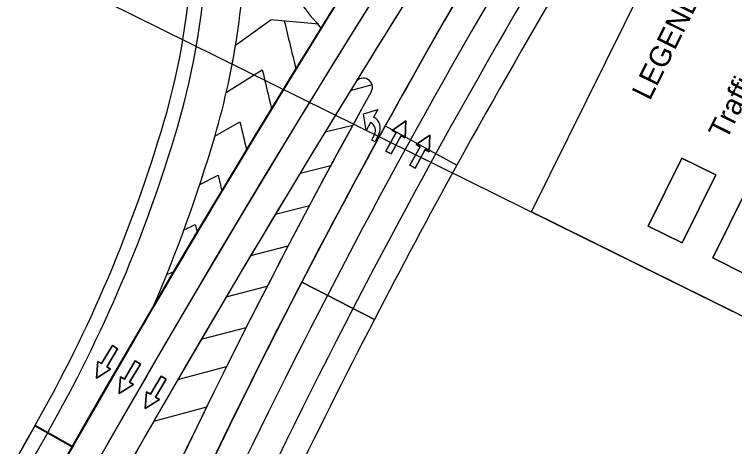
# Model space of a CAD drawing. Extents: x 14090526 to 14125274, y 8637242 to 8677144.
# Drawn here: x 14118917.5 to 14119217.3, y 8668599.6 to 8668779.6 of the extents above; entities that cross this region are included whole.
import ezdxf

# ---------------------------------------------------------------- set-up
doc = ezdxf.new("R2010")
doc.units = 0
for name, color, linetype in [('Cell', 7, 'Continuous'), ('dsn_stg_shd_prev', 7, 'Continuous'), ('dsnNonPlotable', 7, 'Continuous'), ('dsnPaintExistingBrokenLaneLineWhite', 7, 'Continuous'), ('dsnPaintExistingChannelizingLaneWhite', 7, 'Continuous'), ('dsnPaintExistingChannelizingLaneYellow', 7, 'Continuous'), ('dsnPaintExistingEdgeLineRightWhite', 7, 'Continuous'), ('dsnPaintExistingSolidLaneLaneWhite', 7, 'Continuous'), ('dsnShadingPaved', 7, 'Continuous'), ('dsnStgShadingPropPav', 7, 'Continuous'), ('dsnTextOverlapOdd', 7, 'Continuous'), ('Level 2', 7, 'Continuous'), ('Level 5', 7, 'Continuous')]:
    doc.layers.add(name, color=color, linetype=linetype)

msp = doc.modelspace()

# ---------------------------------------------------------------- linework, layer by layer
at = {"layer": 'Cell'}
for p, q in [((14119066.94, 8668736.82), (14119067.1, 8668736.74)), ((14119065.94, 8668734.39), (14119065.66, 8668734.53))]:
    msp.add_line(p, q, dxfattribs=at)
for points in [[(14119062.85, 8668738.26), (14119068.73, 8668740.04), (14119066.94, 8668736.82)], [(14119062.85, 8668738.26), (14119068.73, 8668740.04), (14119066.94, 8668736.82)], [(14119065.66, 8668734.53), (14119063.86, 8668731.31), (14119062.85, 8668738.26)], [(14119065.66, 8668734.53), (14119063.86, 8668731.31), (14119062.85, 8668738.26)], [(14119066.94, 8668736.82), (14119067.1, 8668736.74)], [(14119065.94, 8668734.39), (14119065.66, 8668734.53)], [(14119069.24, 8668729.82), (14119067.61, 8668726.52), (14119066.27, 8668727.19), (14119067.43, 8668729.54)], [(14119069.24, 8668729.82), (14119067.61, 8668726.52), (14119066.27, 8668727.19), (14119067.43, 8668729.54)]]:
    msp.add_lwpolyline(points, dxfattribs=at)
for centre, major_axis in [((14119064.77, 8668732.03), (-2.33, -4.71)), ((14119064.77, 8668732.03), (-2.33, -4.71)), ((14119064.31, 8668731.09), (-1.63, -3.3)), ((14119064.31, 8668731.09), (-1.63, -3.3))]:
    msp.add_ellipse(centre, major_axis=major_axis, ratio=0.9474, start_param=1.570796, end_param=3.141593, dxfattribs=at)
at = {"layer": 'dsn_stg_shd_prev'}
for p, q in [((14119071.87, 8668733.2), (14119101.66, 8668716.8)), ((14118926.04, 8668608.26), (14118941.65, 8668599.39)), ((14118926.13, 8668608.49), (14118941.74, 8668599.61)), ((14118926.13, 8668608.49), (14118941.74, 8668599.61))]:
    msp.add_line(p, q, dxfattribs=at)
for centre, radius, start, end in [((14123732.59, 8665873.82), 5512, 146.41866, 157.1633), ((14123732.59, 8665873.82), 5512, 146.50213, 150.36196), ((14121591.75, 8667345.11), 2876.96, 147.23629, 155.33788), ((14121592.11, 8667345.68), 2876.95, 147.23628, 151.16499), ((14121592.11, 8667345.68), 2842.95, 147.24613, 151.16499), ((14118697.65, 8668817.62), 294, 343.6304, 12.5104), ((14118409.81, 8668902.17), 594, 330.3689, 343.63038), ((14123732.86, 8665874.15), 5530, 150.3689, 156.09911), ((14123732.96, 8665874.38), 5530, 150.3689, 156.09911), ((14123732.59, 8665873.82), 5512, 150.36196, 157.1633)]:
    msp.add_arc(centre, radius, start, end, dxfattribs=at)
at = {"layer": 'dsnNonPlotable'}
msp.add_lwpolyline([(14119315.27, 8668607.09), (14120010, 8670012.23), (14119557.31, 8670236.05), (14118862.58, 8668830.91)], close=True, dxfattribs=at)
at = {"layer": 'dsnPaintExistingBrokenLaneLineWhite'}
for centre, radius, start in [((14121592.11, 8667345.68), 2864.95, 147.15737), ((14123732.96, 8665874.38), 5500, 147.11705)]:
    msp.add_arc(centre, radius, start, 157.1633, dxfattribs=at)
at = {"layer": 'dsnPaintExistingChannelizingLaneWhite'}
for p, q in [((14119009.55, 8668766.85), (14119024.28, 8668777.3)), ((14119044.14, 8668775.58), (14119024.28, 8668777.3)), ((14119005.71, 8668747.22), (14119020.62, 8668756.58)), ((14119000.92, 8668728.83), (14119011.33, 8668734.86)), ((14118994.67, 8668708.79), (14119002.26, 8668712.6)), ((14118988.09, 8668689.91), (14118992.79, 8668692.09)), ((14118980.89, 8668671.25), (14118983.27, 8668672.26))]:
    msp.add_line(p, q, dxfattribs=at)
for centre, radius, start, end in [((14118697.65, 8668817.62), 316, 343.6304, 0.4076), ((14119233.62, 8668936.54), 249, 207.9416, 220.8109), ((14124361.64, 8670051.25), 5482, 193.44292, 193.6584), ((14123732.96, 8665874.38), 5512, 148.26304, 149.67774), ((14124353.66, 8670025.82), 5482, 193.38707, 193.56306), ((14124341.15, 8670017.58), 5482, 193.53196, 193.6584), ((14118409.81, 8668902.17), 616, 336.56541, 343.63038), ((14124330.84, 8670000.44), 5482, 193.58699, 193.6584), ((14124357.11, 8670043.79), 5532, 194.14298, 194.17822), ((14124346.93, 8670026.57), 5532, 194.17092, 194.17822)]:
    msp.add_arc(centre, radius, start, end, dxfattribs=at)
at = {"layer": 'dsnPaintExistingChannelizingLaneYellow'}
for p, q in [((14119066.36, 8668750.3), (14119057.26, 8668747.71)), ((14119046.82, 8668730.65), (14119058.31, 8668733.44)), ((14119036.44, 8668713.55), (14119049.22, 8668716.7)), ((14119026.13, 8668696.42), (14119040.26, 8668699.96)), ((14119015.87, 8668679.24), (14119031.44, 8668683.2)), ((14119005.68, 8668662.04), (14119022.76, 8668666.44)), ((14118995.73, 8668644.44), (14119013.98, 8668649.22)), ((14118985.49, 8668627.51), (14119005.79, 8668632.9)), ((14118975.49, 8668610.19), (14118997.51, 8668616.13))]:
    msp.add_line(p, q, dxfattribs=at)
for centre, radius, start, end in [((14123748.96, 8665864.73), 5506.68, 148.38653, 150.66501), ((14119062.69, 8668749.26), 3.81, 330.9739, 148.3847), ((14121592.11, 8667345.68), 2888.95, 150.97391, 155.3184)]:
    msp.add_arc(centre, radius, start, end, dxfattribs=at)
at = {"layer": 'dsnPaintExistingEdgeLineRightWhite'}
for centre, radius, start, end in [((14121592.11, 8667345.68), 2852.95, 147.15737, 157.1633), ((14118697.65, 8668817.62), 300, 343.6304, 12.5123), ((14118409.81, 8668902.17), 600, 330.3689, 343.63038), ((14123732.96, 8665874.38), 5524, 150.3689, 156.09858)]:
    msp.add_arc(centre, radius, start, end, dxfattribs=at)
at = {"layer": 'dsnPaintExistingSolidLaneLaneWhite'}
msp.add_line((14118975, 8668657.18), (14118941.78, 8668599.59), dxfattribs=at)
msp.add_arc((14121592.11, 8667345.68), 2876.95, 150.94619, 156.23387, dxfattribs=at)
at = {"layer": 'dsnShadingPaved'}
msp.add_line((14118941.78, 8668599.59), (14118931.35, 8668605.52), dxfattribs=at)
for centre, radius, start, end in [((14123732.96, 8665874.38), 5500, 145.2497, 157.1633), ((14123732.96, 8665874.38), 5488, 145.2497, 157.1633), ((14123732.96, 8665874.38), 5500, 146.42378, 157.1633), ((14121592.11, 8667345.68), 2876.95, 147.15737, 157.1633), ((14121592.11, 8667345.68), 2852.95, 147.15737, 157.1633), ((14123655.03, 8665915.77), 5424.12, 146.80648, 157.24675), ((14118697.65, 8668817.62), 300, 343.6304, 12.5123), ((14121592.11, 8667345.68), 2876.95, 149.16283, 157.1633), ((14123732.96, 8665874.38), 5488, 147.75486, 148.38471), ((14123732.96, 8665874.38), 5512, 148.132, 150.3689), ((14119062.69, 8668749.26), 3.81, 330.9739, 148.3847), ((14121592.11, 8667345.68), 2888.95, 150.97391, 156.23389), ((14118409.81, 8668902.17), 600, 330.3689, 343.63038), ((14123732.96, 8665874.38), 5524, 150.3689, 156.09858)]:
    msp.add_arc(centre, radius, start, end, dxfattribs=at)
at = {"layer": 'dsnStgShadingPropPav'}
for p, q in [((14119071.87, 8668733.2), (14119101.66, 8668716.8)), ((14119071.87, 8668733.2), (14119101.66, 8668716.8)), ((14119067.32, 8668652.5), (14119037.13, 8668668.13)), ((14119037.13, 8668668.13), (14119067.32, 8668652.5)), ((14118926.13, 8668608.49), (14118941.74, 8668599.61))]:
    msp.add_line(p, q, dxfattribs=at)
for centre, radius, start, end in [((14123732.59, 8665873.82), 5512, 146.41866, 157.1633), ((14123732.59, 8665873.82), 5512, 146.50213, 150.36196), ((14121591.75, 8667345.11), 2876.96, 147.23629, 155.33788), ((14121592.11, 8667345.68), 2876.95, 147.23628, 151.16499), ((14121592.11, 8667345.68), 2842.95, 147.24613, 151.16499), ((14118697.65, 8668817.62), 294, 343.6304, 12.5104), ((14118409.81, 8668902.17), 594, 330.3689, 343.63038), ((14121592.11, 8667345.68), 2876.95, 151.16499, 152.63404), ((14121592.11, 8667345.68), 2842.95, 151.16499, 152.63404), ((14121592.11, 8667345.68), 2876.95, 152.63404, 155.90343), ((14121592.11, 8667345.68), 2842.95, 152.63404, 155.90343)]:
    msp.add_arc(centre, radius, start, end, dxfattribs=at)
at = {"layer": 'dsnTextOverlapOdd'}
for points in [[(14119132.8, 8668697.31), (14119210.08, 8668853.62), (14119392.55, 8668763.4), (14119315.27, 8668607.09)], [(14119132.8, 8668697.31), (14119210.08, 8668853.62), (14119392.55, 8668763.4), (14119315.27, 8668607.09)], [(14119181.33, 8668691.45), (14119195.33, 8668719.78), (14119209.41, 8668712.82), (14119195.4, 8668684.49)], [(14119209.41, 8668712.82), (14119195.33, 8668719.78), (14119181.33, 8668691.45), (14119195.4, 8668684.49)], [(14119208.22, 8668678.15), (14119222.23, 8668706.49), (14119236.3, 8668699.53), (14119222.29, 8668671.19)], [(14119236.3, 8668699.53), (14119222.23, 8668706.49), (14119208.22, 8668678.15), (14119222.29, 8668671.19)]]:
    msp.add_lwpolyline(points, close=True, dxfattribs=at)
at = {"layer": 'Level 2'}
for points in [[(14119072.11, 8668722.7), (14119074.3, 8668721.49), (14119078.53, 8668729.15), (14119080.17, 8668728.24), (14119080.46, 8668735.22), (14119074.71, 8668731.27), (14119076.35, 8668730.36)], [(14119082.1, 8668716.83), (14119084.28, 8668715.62), (14119088.52, 8668723.28), (14119090.16, 8668722.37), (14119090.45, 8668729.36), (14119084.69, 8668725.4), (14119086.33, 8668724.49)], [(14118960.4, 8668640.37), (14118958.25, 8668641.66), (14118953.77, 8668634.14), (14118952.16, 8668635.1), (14118951.64, 8668628.14), (14118957.52, 8668631.9), (14118955.91, 8668632.86)], [(14118969.91, 8668633.96), (14118967.76, 8668635.25), (14118963.28, 8668627.73), (14118961.67, 8668628.69), (14118961.15, 8668621.72), (14118967.04, 8668625.49), (14118965.43, 8668626.45)], [(14118980.7, 8668627.64), (14118978.55, 8668628.93), (14118974.07, 8668621.41), (14118972.46, 8668622.37), (14118971.94, 8668615.41), (14118977.82, 8668619.17), (14118976.21, 8668620.13)]]:
    msp.add_lwpolyline(points, close=True, dxfattribs=at)
at = {"layer": 'Level 5'}
for points in [[(14119076.35, 8668730.36), (14119074.71, 8668731.27), (14119080.46, 8668735.22), (14119080.17, 8668728.24), (14119078.53, 8668729.15), (14119074.3, 8668721.49), (14119072.11, 8668722.7), (14119076.35, 8668730.36)], [(14119086.33, 8668724.49), (14119084.69, 8668725.4), (14119090.45, 8668729.36), (14119090.16, 8668722.37), (14119088.52, 8668723.28), (14119084.28, 8668715.62), (14119082.1, 8668716.83), (14119086.33, 8668724.49)], [(14118955.91, 8668632.86), (14118957.52, 8668631.9), (14118951.64, 8668628.14), (14118952.16, 8668635.1), (14118953.77, 8668634.14), (14118958.25, 8668641.66), (14118960.4, 8668640.37), (14118955.91, 8668632.86)], [(14118965.43, 8668626.45), (14118967.04, 8668625.49), (14118961.15, 8668621.72), (14118961.67, 8668628.69), (14118963.28, 8668627.73), (14118967.76, 8668635.25), (14118969.91, 8668633.96), (14118965.43, 8668626.45)], [(14118976.21, 8668620.13), (14118977.82, 8668619.17), (14118971.94, 8668615.41), (14118972.46, 8668622.37), (14118974.07, 8668621.41), (14118978.55, 8668628.93), (14118980.7, 8668627.64), (14118976.21, 8668620.13)]]:
    msp.add_lwpolyline(points, dxfattribs=at)

# ---------------------------------------------------------------- texts
at = {"layer": 'dsnTextOverlapOdd'}
for s, p in [('Traffic Lanes', (14119213.88, 8668726.97)), ('LEGEND', (14119181.97, 8668743.36))]:
    msp.add_text(s, height=8.75, rotation=63.6912, dxfattribs=at).set_placement(p)

doc.saveas('drawing.dxf')
